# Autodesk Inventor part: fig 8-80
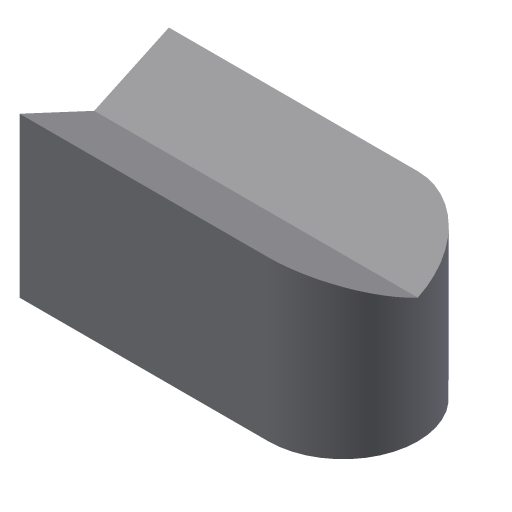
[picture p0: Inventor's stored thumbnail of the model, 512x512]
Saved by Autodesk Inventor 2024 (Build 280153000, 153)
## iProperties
Created: 2011-07
Part Number: fig 8-80
Material: Generic
Document SubType Name: Modeling
Designer: CadCim
Density: 1 g/cm^3
Appearance: Default
Author: CadCim
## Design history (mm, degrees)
sketch "Sketch1"
  geometry: L1 (-16, 5)-(-16, -7); L2 (-16, -7)-(4, -7); L3 (4, 5)-(-16, 5); A1 r 6 centre (4, -1) between (4, -7) and (4, 5); 1 further point
  constraints: 6 end point, 2 point on circle, 2 tangent, 1 centre point, 1 parallel, 1 perpendicular, 1 vertical
extrude "Extrusion1" new body sketch "Sketch1" distance "d0" = 10; taper "d1" = 0 deg
sketch "Sketch2"
  geometry: L1 (-16, -1)-(10, -1); 1 further point
  constraints: 2 end point, 1 horizontal
feature "FaceDraft1" sketch "Sketch2" dims angle "d2" = -25 deg
body "Solid1"
